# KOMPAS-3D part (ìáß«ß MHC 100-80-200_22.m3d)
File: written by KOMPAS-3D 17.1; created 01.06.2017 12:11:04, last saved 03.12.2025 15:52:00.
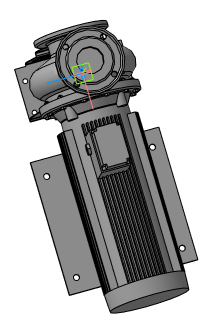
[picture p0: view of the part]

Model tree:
1. Операция без истории:4

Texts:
  ООО АДЛ ГРУПП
